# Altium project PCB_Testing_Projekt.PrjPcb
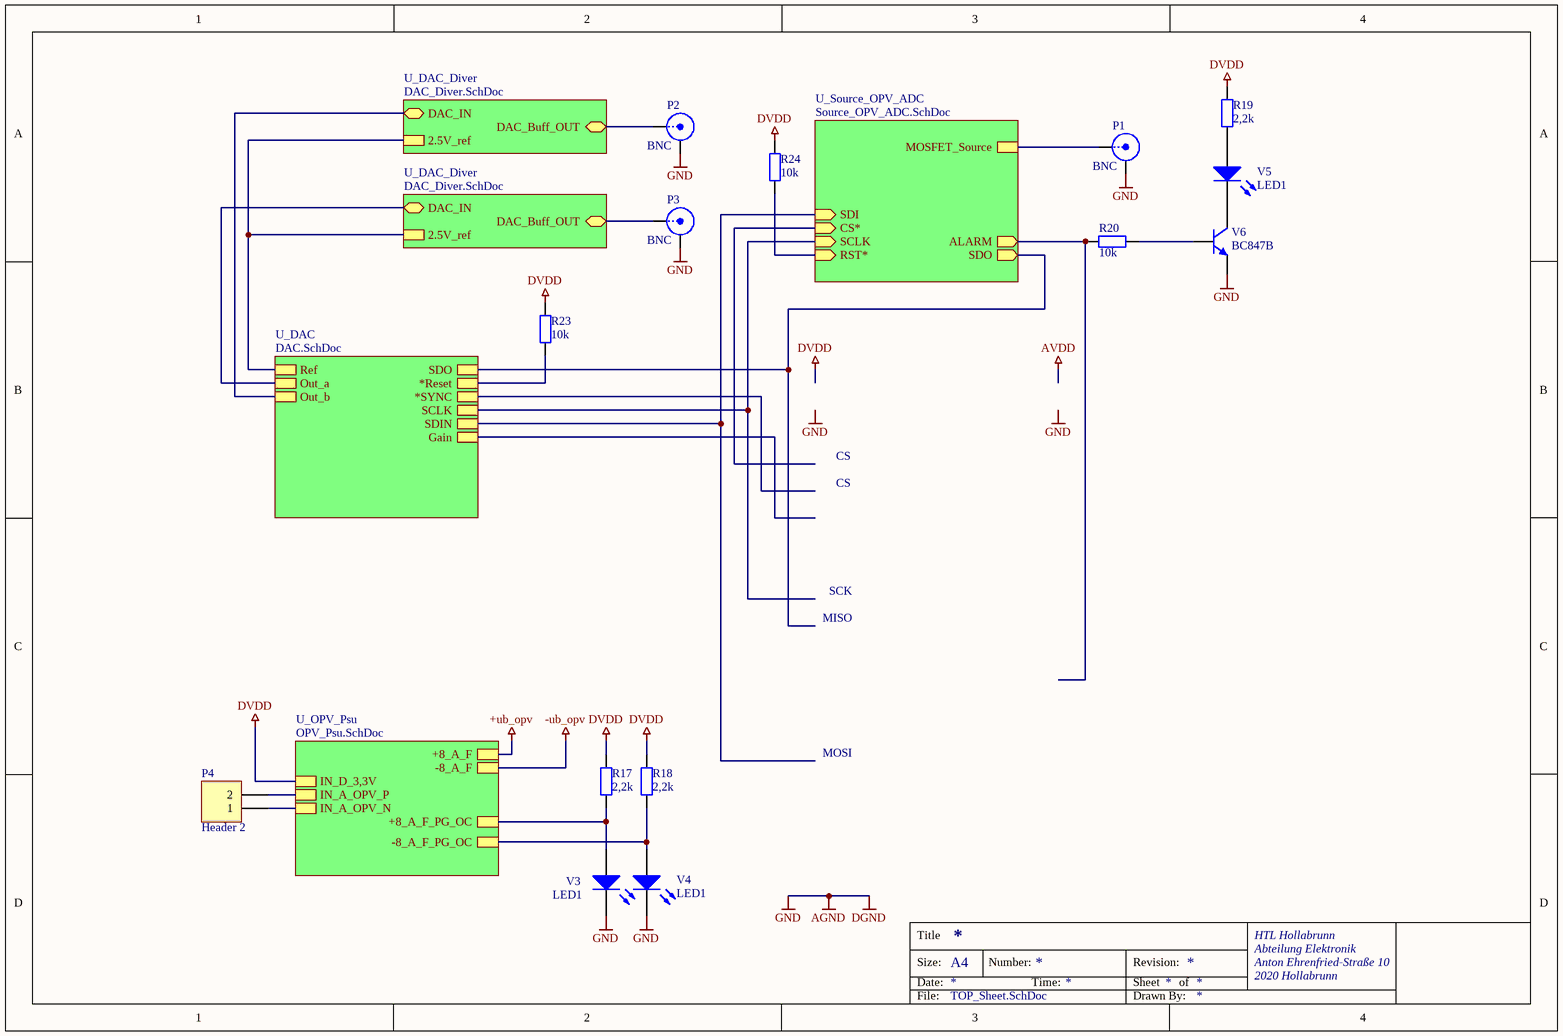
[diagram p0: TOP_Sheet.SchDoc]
5 sheets, 67 parts. Net scope: hierarchical (ports join the sheet entries above them; power ports are global).
Board file: PCB1.PcbDoc
Sheets:
  TOP_Sheet.SchDoc
    U_Source_OPV_ADC = Source_OPV_ADC.SchDoc
    U_OPV_Psu = OPV_Psu.SchDoc
    U_DAC_Diver = DAC_Diver.SchDoc
    U_DAC_Diver = DAC_Diver.SchDoc
    U_DAC = DAC.SchDoc

## Sheet TOP_Sheet.SchDoc
size A4; Organization: HTL Hollabrunn; Address1: Abteilung Elektronik; Address2: Anton Ehrenfried-Straße 10; Address3: 2020 Hollabrunn; SPICEModelCacheBIRIWKQP: <root> / <DocumentId>BIRIWKQP</DocumentId> / <CacheFrame Number="0"> / <Model Name="led1" Kind="MDL"> / <Text>*Typ RED GaAs LED: Vf=1.7V Vr=4V If=40mA trr=3uS / *LED Pinout: 1=A, 2=K / .MODEL LED1 D (IS=93.2P RS=42M N=3.73 BV=4 IBV=10U / + CJO=2.97P VJ=.75 M=.333 TT=4.32U)</Text> / </Model> / <Model Name="qbc847b" Kind="MDL"> / <Text>* / .MODEL QBC847B NPN( / +     IS = 1.822E-14 / +     NF = 0.9932 / +     ISE = 2.894E-16 / +     NE = 1.4 / +     BF = 324.4 / +     IKF = 0.109 / +     VAF = 82 / +     NR = 0.9931 / +     ISC = 9.982E-12 / +     NC = 1.763 / +     BR = 8.29 / +     IKR = 0.09 / +     VAR = 17.9 / +     RB = 10 / +     IRB = 5E-06 / +     RBM = 5 / +     RE = 0.649 / +     RC = 0.7014 / +     XTB = 0 / +     EG = 1.11 / +     XTI = 3 / +     CJE = 1.244E-11 / +     VJE = 0.7579 / +     MJE = 0.3656 / +     TF = 4.908E-10 / +     XTF = 9.51 / +     VTF = 2.927 / +     ITF = 0.3131 / +     PTF = 0 / +     CJC = 3.347E-12 / +     VJC = 0.5463 / +     MJC = 0.391 / +     XCJC = 0.6193 / +     TR = 9E-08 / +     CJS = 0 / +     VJS = 0.75 / +     MJS = 0.333 / +     FC = 0.979)</Text> / </Model> / </CacheFrame> / </root>

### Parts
P1  BNC  [BNC_RA CON]
P2  BNC  [BNC_RA CON]
P3  BNC  [BNC_RA CON]
P4  Header 2  [HDR1X2]
R17  2,2k  [C1206-KUE]
R18  2,2k  [C1206-KUE]
R19  2,2k  [C1206-KUE]
R20  10k  [C1206-KUE]
R23  10k  [C1206-KUE]
R24  10k  [C1206-KUE]
V3  LED1  [LED-1]
V4  LED1  [LED-1]
V5  LED1  [LED-1]
V6  BC847B  [SOT23-KUE]

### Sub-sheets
U_DAC = DAC.SchDoc: Ref, Out_a, Out_b, SDIN, SDO, SCLK, *SYNC, Gain, *Reset
U_DAC_Diver = DAC_Diver.SchDoc: DAC_IN (bidir), DAC_Buff_OUT (bidir), 2.5V_ref
U_DAC_Diver = DAC_Diver.SchDoc: DAC_IN (bidir), DAC_Buff_OUT (bidir), 2.5V_ref
U_OPV_Psu = OPV_Psu.SchDoc: IN_A_OPV_P, +8_A_F, IN_A_OPV_N, IN_D_3,3V, -8_A_F, -8_A_F_PG_OC, +8_A_F_PG_OC
U_Source_OPV_ADC = Source_OPV_ADC.SchDoc: MOSFET_Source, SDI (in), CS* (in), SCLK (in), SDO (out), ALARM (out), RST* (in)

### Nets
AGND: P1.2(Y) P2.2(Y) P3.2(Y) V3.2(K) V4.2(K) V6.2(E)  [also labelled DGND, GND]
DVDD: R17.1 R18.1 R19.1 R23.1 R24.1 ; sheet U_OPV_Psu/IN_D_3,3V  [project net Digital33V]
NetC6_1: P1.1(X) ; sheet U_Source_OPV_ADC/MOSFET_Source
NetC14_2: sheet U_DAC_Diver/2.5V_ref, sheet U_DAC_Diver/2.5V_ref, sheet U_DAC/Ref
NetP2_1: P2.1(X) ; sheet U_DAC_Diver/DAC_Buff_OUT
NetP3_1: P3.1(X) ; sheet U_DAC_Diver/DAC_Buff_OUT
NetP4_1: P4.1 ; sheet U_OPV_Psu/IN_A_OPV_N
NetP4_2: P4.2 ; sheet U_OPV_Psu/IN_A_OPV_P
NetR2_1: R24.2 ; sheet U_Source_OPV_ADC/RST*
NetR7_U_DAC_Diver1_2: sheet U_DAC_Diver/DAC_IN, sheet U_DAC/Out_b
NetR7_U_DAC_Diver2_2: sheet U_DAC_Diver/DAC_IN, sheet U_DAC/Out_a
NetR17_2: R17.2 V3.1(A) ; sheet U_OPV_Psu/+8_A_F_PG_OC
NetR18_2: R18.2 V4.1(A) ; sheet U_OPV_Psu/-8_A_F_PG_OC
NetR19_2: R19.2 V5.1(A)
NetR20_1: R20.1 ; sheet U_Source_OPV_ADC/ALARM
NetR20_2: R20.2 V6.1(B)
NetR23_2: R23.2 ; sheet U_DAC/*Reset
NetU1_10: sheet U_Source_OPV_ADC/SDI, sheet U_DAC/SDIN
NetU1_12: sheet U_Source_OPV_ADC/SCLK, sheet U_DAC/SCLK
NetU1_13: sheet U_Source_OPV_ADC/SDO, sheet U_DAC/SDO
NetV5_2: V5.2(K) V6.3(C)

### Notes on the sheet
- CS
- MISO
- SCK
- MOSI
- Labels drawn without touching a wire or pin: GND

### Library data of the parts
P1-P3 = BNC: BNC Elbow Connector
P4 = Header 2: Header, 2-Pin
R17-R20 R23 R24 = ResistorSMD: Resistor SMD; Manufacturer: AVX; Bezeichnung: SMD Wid. 1/8W 2%
V3-V5 = LED1: Typical RED GaAs LED
V6 = BC847B: NPN General-purpose Transistor SMD; Manufacturer: NXP; Bezeichnung: NPN SMD 45V 0.1A 0.25W

## Sheet Source_OPV_ADC.SchDoc
size A4; Organization: HTL Hollabrunn; Address1: Abteilung Elektronik; Address2: Anton Ehrenfried-Straße 10; Address3: 2020 Hollabrunn; SheetNumber: 1; SheetTotal: 1; SPICEModelCacheDVQSEWCR: <root> / <DocumentId>DVQSEWCR</DocumentId> / <CacheFrame Number="0"> / <Model Name="ua741" Kind="CKT"> / <Text>*==================================================== / *uA741 / *Sngl GenPurpose OpAmp pkg:DIP8 3,2,7,4,6. pkg:CAN8 3,2,7,4,6. / * Connections: / *             Non-Inverting Input / *             ¦ Inverting Input / *             ¦ ¦ Positive Power Supply / *             ¦ ¦ ¦ Negative Power Supply / *             ¦ ¦ ¦ ¦ Output / *             ¦ ¦ ¦ ¦ ¦ / .SUBCKT UA741 1 2 3 4 5 / C1   11 12 4.664E-12 / C2    6  7 20E-12 / DC    5 53 DX / DE   54  5 DX / DLP  90 91 DX / DLN  92 90 DX / DP    4  3 DX / BGND 99  0 V=V(3)*.5 + V(4)*.5 / BB    7 99 I=I(VB)*10.61E6 - I(VC)*10E6 + I(VE)*10E6 + / +              I(VLP)*10E6 - I(VLN)*10E6 / GA    6  0 11 12 137.7E-6 / GCM   0  6 10 99 2.574E-9 / IEE  10  4 DC 10.16E-6 / HLIM 90  0 VLIM 1K / Q1   11  2 13 QX / Q2   12  1 14 QX / R2    6  9 100E3 / RC1   3 11 7.957E3 / RC2   3 12 7.957E3 / RE1  13 10 2.74E3 / RE2  14 10 2.74E3 / REE  10 99 19.69E6 / RO1   8  5 150 / RO2   7 99 150 / RP    3  4 18.11E3 / VB    9  0 DC 0 / VC    3 53 DC 2.6 / VE   54  4 DC 2.6 / VLIM  7  8 DC 0 / VLP  91  0 DC 25 / VLN   0 92 DC 25 / .MODEL DX D(IS=800E-18) / .MODEL QX NPN(IS=800E-18 BF=62.5) / .ENDS UA741</Text> / </Model> / <Model Name="cap" Kind="MDL"> / <Text>*Default semiconductor capacitor / .MODEL CAP C()</Text> / </Model> / </CacheFrame> / </root>
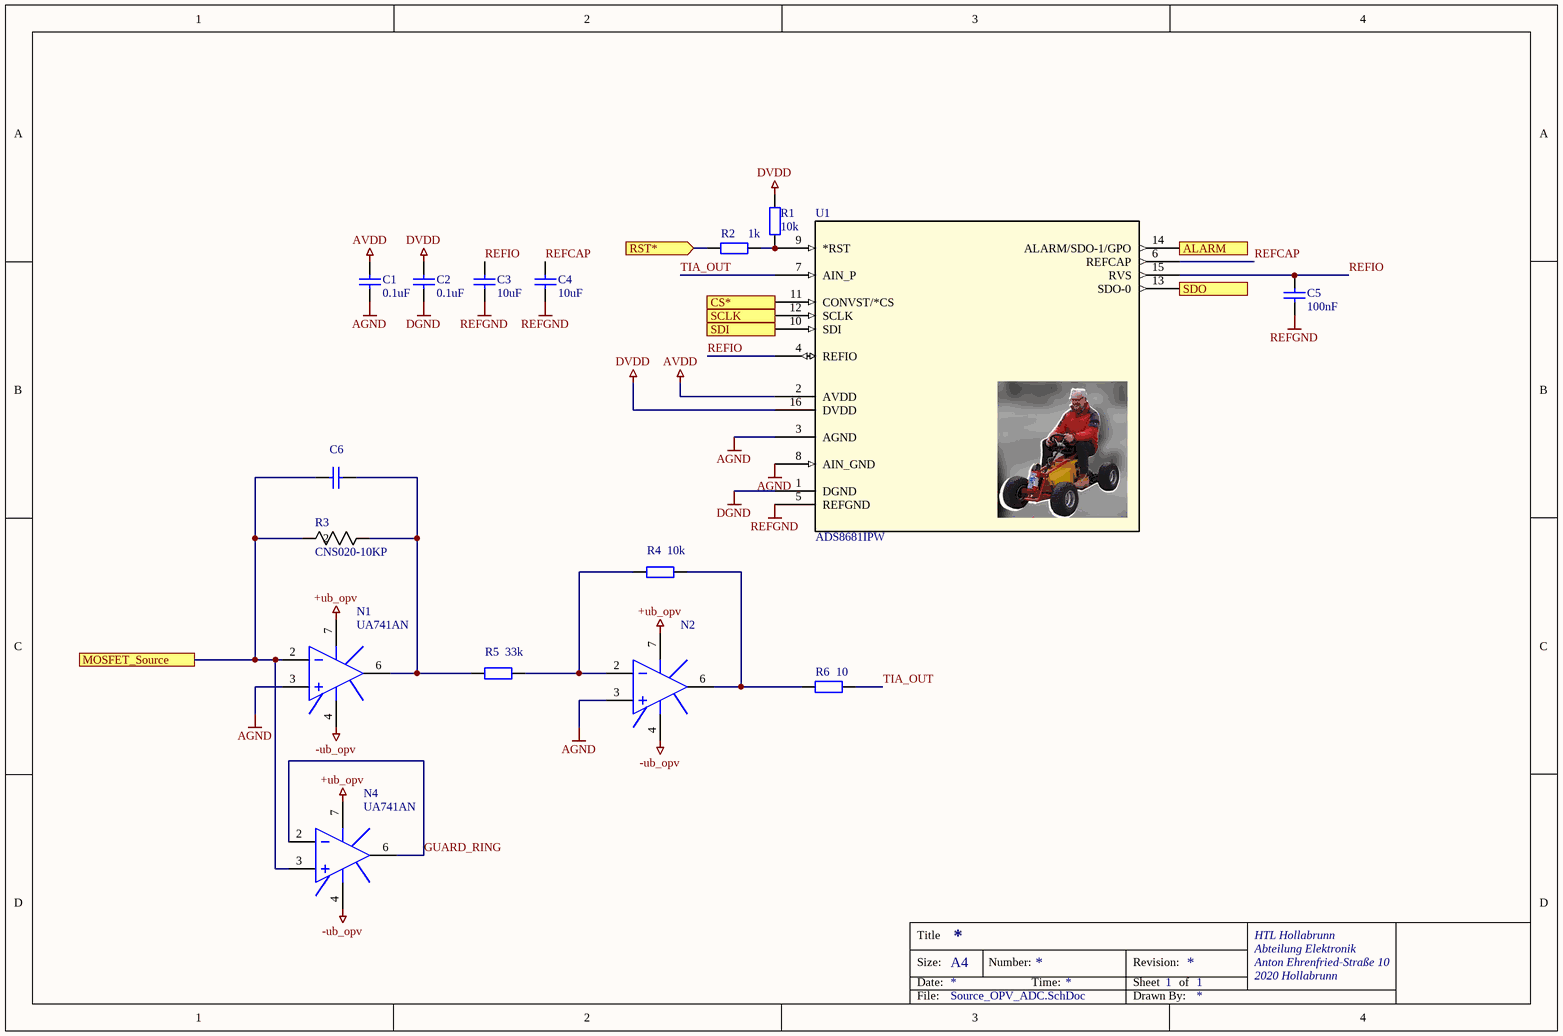
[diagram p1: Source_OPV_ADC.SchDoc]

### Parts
C1  0.1uF  [C1206-KUE]
C2  0.1uF  [C1206-KUE]
C3  10uF  [C1206-KUE]
C4  10uF  [C1206-KUE]
C5  100nF  [C1206-KUE]
C6  100nF  [C1206-KUE]  (value not drawn)
N1  UA741AN  [DIP8]
N2  UA741AN  [DIP8]  (value not drawn)
N4  UA741AN  [DIP8]
R1  10k  [C1206-KUE]
R2  1k  [C1206-KUE]
R3  CNS020-10KP  [RES_CNS020_VIS]
R4  10k  [C1206-KUE]
R5  33k  [C1206-KUE]
R6  10  [C1206-KUE]
U1  ADS8681IPW  [PW16_TEX]

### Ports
ALARM (out), CS* (in), MOSFET_Source, RST* (in), SCLK (in), SDI (in), SDO (out)

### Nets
+ub_opv: N1.7(V+) N2.7(V+) N4.7(V+)  [project net pos_out]
-ub_opv: N1.4(V-) N2.4(V-) N4.4(V-)  [project net neg_out]
AGND: C1.1 C2.1 N1.3(IN+) N2.3(IN+) U1.1(DGND) U1.3(AGND) U1.8(AIN_GND)  [also labelled DGND]
AVDD: C1.2 U1.2(AVDD)
DVDD: C2.2 R1.1 U1.16(DVDD)  [project net Digital33V]
REFGND: C3.1 C4.1 C5.1 U1.5(REFGND)
GUARD_RING: N4.2(IN-) N4.6(OUT)
REFCAP: C4.2 U1.6(REFCAP)
REFIO: C3.2 C5.2 U1.4(REFIO) U1.15(RVS)
TIA_OUT: R6.1 U1.7(AIN_P)
NetC6_1: C6.1 N1.2(IN-) N4.3(IN+) R3.2 ; port MOSFET_Source
NetC6_2: C6.2 N1.6(OUT) R3.1 R5.2
NetN2_2: N2.2(IN-) R4.2 R5.1
NetN2_6: N2.6(OUT) R4.1 R6.2
NetR1_2: R1.2 R2.2 U1.9(*RST)
NetR2_1: R2.1 ; port RST*
NetR20_1: U1.14(ALARM/SDO-1/GPO) ; port ALARM
NetU1_10: U1.10(SDI) ; port SDI
NetU1_11: U1.11(CONVST/*CS) ; port CS*
NetU1_12: U1.12(SCLK) ; port SCLK
NetU1_13: U1.13(SDO-0) ; port SDO

Not connected (* = marked no-connect by the designer): N1 1(OS_NULL) 5(OS_NULL) 8(NC); N2 1(OS_NULL) 5(OS_NULL) 8(NC); N4 1(OS_NULL) 5(OS_NULL) 8(NC)

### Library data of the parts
C1-C6 = Capacitor: Manufacturer: Kemet; Bezeichnung: Kerko +-10% 63V
N1 N2 N4 = UA741AN: General-Purpose Single Operational Amplifier
R1 R2 R4-R6 = ResistorSMD: as R17 on sheet TOP_Sheet
R3 = CNS020-10KP: CNS 020 10K 0,02% e2; Manufacturer_Name: Vishay
U1 = ADS8681IPW: 16-bit, 1MSPS 1-ch SAR ADC with programmable (Â±12V, Â±10V, Â±6V, Â±5V, Â±2.5V) input ranges on 5V supply 16-TSSOP -40 to 125; Manufacturer_Name: Texas Instruments

## Sheet OPV_Psu.SchDoc
size A4; Organization: HTL Hollabrunn; Address1: Abteilung Elektronik; Address2: Anton Ehrenfried-Straße 10; Address3: 2020 Hollabrunn; SPICEModelCacheKALKJBRQ: <root> / <DocumentId>KALKJBRQ</DocumentId> / <CacheFrame Number="0"> / <Model Name="cap" Kind="MDL"> / <Text>*Default semiconductor capacitor / .MODEL CAP C()</Text> / </Model> / <Model Name="qbc847b" Kind="MDL"> / <Text>* / .MODEL QBC847B NPN( / +     IS = 1.822E-14 / +     NF = 0.9932 / +     ISE = 2.894E-16 / +     NE = 1.4 / +     BF = 324.4 / +     IKF = 0.109 / +     VAF = 82 / +     NR = 0.9931 / +     ISC = 9.982E-12 / +     NC = 1.763 / +     BR = 8.29 / +     IKR = 0.09 / +     VAR = 17.9 / +     RB = 10 / +     IRB = 5E-06 / +     RBM = 5 / +     RE = 0.649 / +     RC = 0.7014 / +     XTB = 0 / +     EG = 1.11 / +     XTI = 3 / +     CJE = 1.244E-11 / +     VJE = 0.7579 / +     MJE = 0.3656 / +     TF = 4.908E-10 / +     XTF = 9.51 / +     VTF = 2.927 / +     ITF = 0.3131 / +     PTF = 0 / +     CJC = 3.347E-12 / +     VJC = 0.5463 / +     MJC = 0.391 / +     XCJC = 0.6193 / +     TR = 9E-08 / +     CJS = 0 / +     VJS = 0.75 / +     MJS = 0.333 / +     FC = 0.979)</Text> / </Model> / </CacheFrame> / </root>
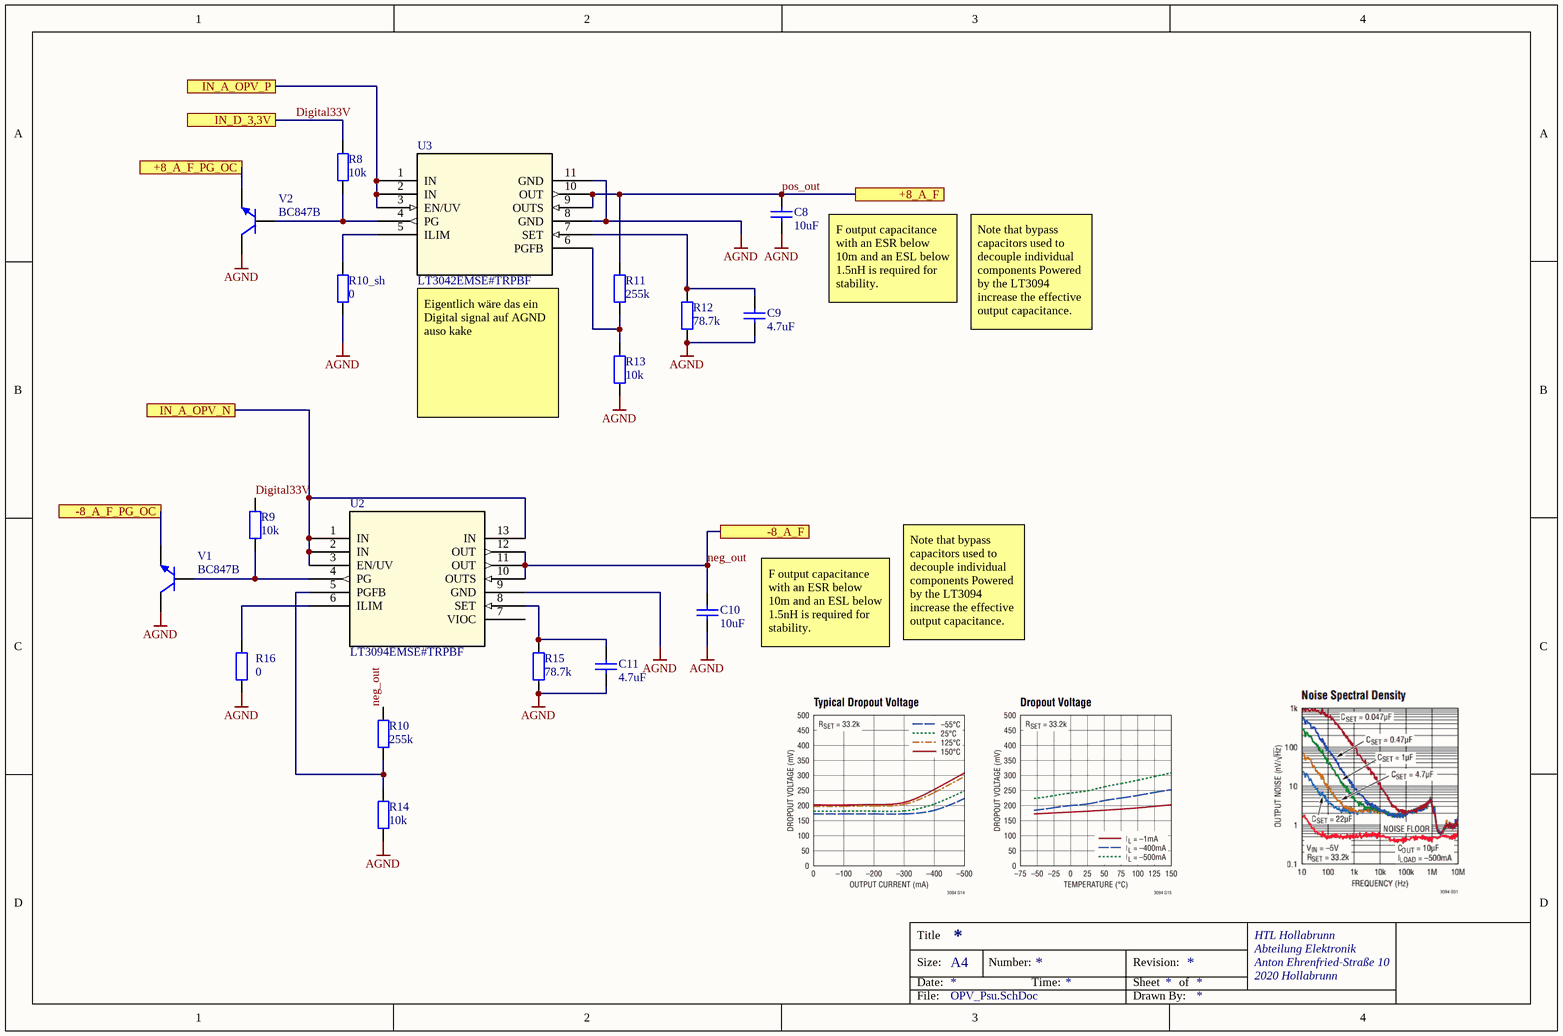
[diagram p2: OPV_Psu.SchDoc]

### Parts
C8  10uF  [C1206-KUE]
C9  4.7uF  [C1206-KUE]
C10  10uF  [C1206-KUE]
C11  4.7uF  [C1206-KUE]
R8  10k  [C1206-KUE]
R9  10k  [C1206-KUE]
R10  255k  [C1206-KUE]
R10_sh  0  [C1206-KUE]
R11  255k  [C1206-KUE]
R12  78.7k  [C1206-KUE]
R13  10k  [C1206-KUE]
R14  10k  [C1206-KUE]
R15  78.7k  [C1206-KUE]
R16  0  [C1206-KUE]
U2  LT3094EMSE#TRPBF  [MSE_05-08-1666_ADI]
U3  LT3042EMSE#TRPBF  [05-08-1664_ADI]
V1  BC847B  [SOT23-KUE]
V2  BC847B  [SOT23-KUE]

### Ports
+8_A_F, +8_A_F_PG_OC, -8_A_F, -8_A_F_PG_OC, IN_A_OPV_N, IN_A_OPV_P, IN_D_3,3V

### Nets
AGND: C8.1 C9.1 C10.1 C11.1 R10_sh.2 R12.2 R13.2 R14.2 R15.2 R16.2 U2.9(GND) U3.8(GND) U3.11(GND) V1.3(C) V2.3(C)
Digital33V: R8.1 R9.1 ; port IN_D_3,3V
neg_out: C10.2 R10.1 U2.10(OUTS) U2.11(OUT) U2.12(OUT) ; port -8_A_F
pos_out: C8.2 R11.1 U3.9(OUTS) U3.10(OUT) ; port +8_A_F
NetC9_2: C9.2 R12.1 U3.7(SET)
NetC11_2: C11.2 R15.1 U2.8(SET)
NetP4_1: U2.1(IN) U2.2(IN) U2.3(EN/UV) U2.13(IN) ; port IN_A_OPV_N
NetP4_2: U3.1(IN) U3.2(IN) U3.3(EN/UV) ; port IN_A_OPV_P
NetR8_2: R8.2 U3.4(PG) V2.1(B)
NetR9_2: R9.2 U2.4(PG) V1.1(B)
NetR10_2: R10.2 R14.1 U2.5(PGFB)
NetR10_sh_1: R10_sh.1 U3.5(ILIM)
NetR11_2: R11.2 R13.1 U3.6(PGFB)
NetR16_1: R16.1 U2.6(ILIM)
NetR17_2: V2.2(E) ; port +8_A_F_PG_OC
NetR18_2: V1.2(E) ; port -8_A_F_PG_OC

Not connected (* = marked no-connect by the designer): U2 7(VIOC)

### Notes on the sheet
- F output capacitance with an ESR below 10m and an ESL below 1.5nH is required for stability.
- Note that bypass capacitors used to decouple individual components Powered by the LT3094 increase the effective output capacitance.
- Eigentlich wäre das ein Digital signal auf AGND auso kake

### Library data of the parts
C8-C11 = Capacitor: as C1 on sheet Source_OPV_ADC
R8-R10 R10_sh R11-R16 = ResistorSMD: as R17 on sheet TOP_Sheet
U2 = LT3094EMSETRPBF: âˆ’20V, 500mA, Ultralow Noise, Ultrahigh PSRR Negative Linear Regulator; Manufacturer_Name: Analog Devices Inc
U3 = LT3042EMSETRPBF: 20V, 200mA, Ultralow Noise, Ultrahigh PSRR RF Linear Regulator; Manufacturer_Name: Analog Devices Inc
V1 V2 = BC847B: as V6 on sheet TOP_Sheet

## Sheet DAC_Diver.SchDoc
size A4; Organization: HTL Hollabrunn; Address1: Abteilung Elektronik; Address2: Anton Ehrenfried-Straße 10; Address3: 2020 Hollabrunn; SPICEModelCacheETVKZAQX: <root> / <DocumentId>ETVKZAQX</DocumentId> / <CacheFrame Number="0"> / <Model Name="cap" Kind="MDL"> / <Text>*Default semiconductor capacitor / .MODEL CAP C()</Text> / </Model> / <Model Name="ua741" Kind="CKT"> / <Text>*==================================================== / *uA741 / *Sngl GenPurpose OpAmp pkg:DIP8 3,2,7,4,6. pkg:CAN8 3,2,7,4,6. / * Connections: / *             Non-Inverting Input / *             ¦ Inverting Input / *             ¦ ¦ Positive Power Supply / *             ¦ ¦ ¦ Negative Power Supply / *             ¦ ¦ ¦ ¦ Output / *             ¦ ¦ ¦ ¦ ¦ / .SUBCKT UA741 1 2 3 4 5 / C1   11 12 4.664E-12 / C2    6  7 20E-12 / DC    5 53 DX / DE   54  5 DX / DLP  90 91 DX / DLN  92 90 DX / DP    4  3 DX / BGND 99  0 V=V(3)*.5 + V(4)*.5 / BB    7 99 I=I(VB)*10.61E6 - I(VC)*10E6 + I(VE)*10E6 + / +              I(VLP)*10E6 - I(VLN)*10E6 / GA    6  0 11 12 137.7E-6 / GCM   0  6 10 99 2.574E-9 / IEE  10  4 DC 10.16E-6 / HLIM 90  0 VLIM 1K / Q1   11  2 13 QX / Q2   12  1 14 QX / R2    6  9 100E3 / RC1   3 11 7.957E3 / RC2   3 12 7.957E3 / RE1  13 10 2.74E3 / RE2  14 10 2.74E3 / REE  10 99 19.69E6 / RO1   8  5 150 / RO2   7 99 150 / RP    3  4 18.11E3 / VB    9  0 DC 0 / VC    3 53 DC 2.6 / VE   54  4 DC 2.6 / VLIM  7  8 DC 0 / VLP  91  0 DC 25 / VLN   0 92 DC 25 / .MODEL DX D(IS=800E-18) / .MODEL QX NPN(IS=800E-18 BF=62.5) / .ENDS UA741</Text> / </Model> / </CacheFrame> / </root>
Used 2 times, as channels U_DAC_Diver, U_DAC_Diver. Parts and nets are listed once, with the designators drawn on the sheet.
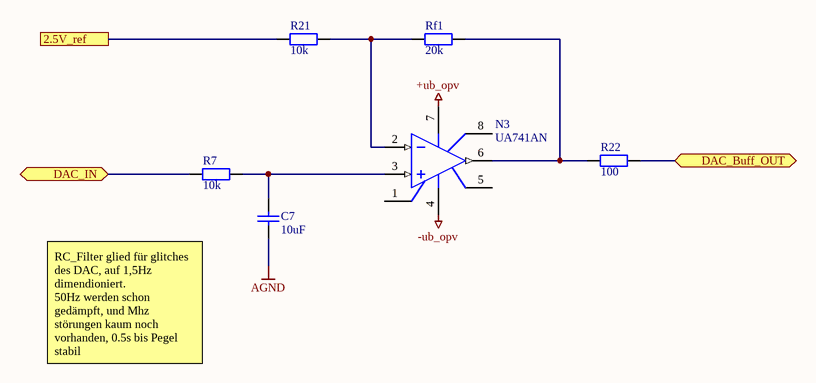
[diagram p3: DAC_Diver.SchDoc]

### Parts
C7  10uF  [C1206-KUE]
N3  UA741AN  [DIP8]
R7  10k  [C1206-KUE]
R21  10k  [C1206-KUE]
R22  100  [C1206-KUE]
Rf1  20k  [C1206-KUE]

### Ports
2.5V_ref, DAC_Buff_OUT (bidir), DAC_IN (bidir)

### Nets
+ub_opv: N3.7(V+)
-ub_opv: N3.4(V-)
AGND: C7.1
2.5V_ref: R21.2 ; port 2.5V_ref
DAC_Buff_OUT: R22.1 ; port DAC_Buff_OUT
DAC_IN: R7.2 ; port DAC_IN
NetC7_2: C7.2 N3.3(IN+) R7.1
NetN3_2: N3.2(IN-) R21.1 Rf1.2
NetN3_6: N3.6(OUT) R22.2 Rf1.1

Not connected (* = marked no-connect by the designer): N3 1(OS_NULL) 5(OS_NULL) 8(NC)

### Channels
U_DAC_Diver: designators end in _U_DAC_Diver2; ports 2.5V_ref=NetC14_2 DAC_Buff_OUT=NetP3_1 DAC_IN=NetR7_U_DAC_Diver2_2
U_DAC_Diver: designators end in _U_DAC_Diver1; ports 2.5V_ref=NetC14_2 DAC_Buff_OUT=NetP2_1 DAC_IN=NetR7_U_DAC_Diver1_2

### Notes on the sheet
- RC_Filter glied für glitches des DAC, auf 1,5Hz dimendioniert.
  50Hz werden schon gedämpft, und Mhz störungen kaum noch vorhanden, 0.5s bis Pegel stabil

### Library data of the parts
C7 = Capacitor: as C1 on sheet Source_OPV_ADC
N3 = UA741AN: as N1 on sheet Source_OPV_ADC
R7 R21 R22 Rf1 = ResistorSMD: as R17 on sheet TOP_Sheet

## Sheet DAC.SchDoc
size A4; Organization: HTL Hollabrunn; Address1: Abteilung Elektronik; Address2: Anton Ehrenfried-Straße 10; Address3: 2020 Hollabrunn; SPICEModelCacheALEDFFPD: <root> / <DocumentId>ALEDFFPD</DocumentId> / <CacheFrame Number="0"> / <Model Name="cap" Kind="MDL"> / <Text>*Default semiconductor capacitor / .MODEL CAP C()</Text> / </Model> / </CacheFrame> / </root>
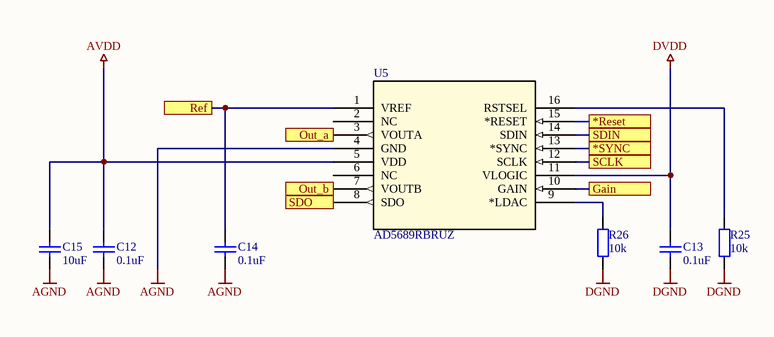
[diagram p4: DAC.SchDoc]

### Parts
C12  0.1uF  [C1206-KUE]
C13  0.1uF  [C1206-KUE]
C14  0.1uF  [C1206-KUE]
C15  10uF  [C1206-KUE]
R25  10k  [C1206-KUE]
R26  10k  [C1206-KUE]
U5  AD5689RBRUZ  [RU_16_ADI]

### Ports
*Reset, *SYNC, Gain, Out_a, Out_b, Ref, SCLK, SDIN, SDO

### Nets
AGND: C12.1 C13.1 C14.1 C15.1 R25.2 R26.2 U5.4(GND)  [also labelled DGND]
AVDD: C12.2 C15.2 U5.5(VDD)
DVDD: C13.2 U5.11(VLOGIC)  [project net Digital33V]
NetC14_2: C14.2 U5.1(VREF) ; port Ref
NetR7_U_DAC_Diver1_2: U5.7(VOUTB) ; port Out_b
NetR7_U_DAC_Diver2_2: U5.3(VOUTA) ; port Out_a
NetR23_2: U5.15(*RESET) ; port *Reset
NetR25_1: R25.1 U5.16(RSTSEL)
NetR26_1: R26.1 U5.9(*LDAC)
NetU1_10: U5.14(SDIN) ; port SDIN
NetU1_12: U5.12(SCLK) ; port SCLK
NetU1_13: U5.8(SDO) ; port SDO
NetU5_10: U5.10(GAIN) ; port Gain
NetU5_13: U5.13(*SYNC) ; port *SYNC

Not connected (* = marked no-connect by the designer): U5 2(NC) 6(NC)

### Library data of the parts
C12-C15 = Capacitor: as C1 on sheet Source_OPV_ADC
R25 R26 = ResistorSMD: as R17 on sheet TOP_Sheet
U5 = AD5689RBRUZ: Dual, 16-Bit nanoDAC+ with 2 ppm/Â°C Reference, SPI Interface; Manufacturer_Name: Analog Devices Inc

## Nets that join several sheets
AGND: TOP_Sheet (6 pins), Source_OPV_ADC (7 pins), OPV_Psu (15 pins), U_DAC_Diver (C7_U_DAC_Diver2.1), U_DAC_Diver (C7_U_DAC_Diver1.1), DAC (7 pins)
AVDD: Source_OPV_ADC (C1.2 U1.2), DAC (C12.2 C15.2 U5.5)
Digital33V: TOP_Sheet (5 pins), Source_OPV_ADC (C2.2 R1.1 U1.16), OPV_Psu (R8.1 R9.1), DAC (C13.2 U5.11)
neg_out: Source_OPV_ADC (N1.4 N2.4 N4.4), OPV_Psu (5 pins), U_DAC_Diver (N3_U_DAC_Diver2.4), U_DAC_Diver (N3_U_DAC_Diver1.4)
pos_out: Source_OPV_ADC (N1.7 N2.7 N4.7), OPV_Psu (C8.2 R11.1 U3.9 U3.10), U_DAC_Diver (N3_U_DAC_Diver2.7), U_DAC_Diver (N3_U_DAC_Diver1.7)
NetC6_1: TOP_Sheet (P1.1), Source_OPV_ADC (C6.1 N1.2 N4.3 R3.2)
NetC14_2: U_DAC_Diver (R21_U_DAC_Diver2.2), U_DAC_Diver (R21_U_DAC_Diver1.2), DAC (C14.2 U5.1)
NetP2_1: TOP_Sheet (P2.1), U_DAC_Diver (R22_U_DAC_Diver1.1)
NetP3_1: TOP_Sheet (P3.1), U_DAC_Diver (R22_U_DAC_Diver2.1)
NetP4_1: TOP_Sheet (P4.1), OPV_Psu (U2.1 U2.2 U2.3 U2.13)
NetP4_2: TOP_Sheet (P4.2), OPV_Psu (U3.1 U3.2 U3.3)
NetR2_1: TOP_Sheet (R24.2), Source_OPV_ADC (R2.1)
NetR7_U_DAC_Diver1_2: U_DAC_Diver (R7_U_DAC_Diver1.2), DAC (U5.7)
NetR7_U_DAC_Diver2_2: U_DAC_Diver (R7_U_DAC_Diver2.2), DAC (U5.3)
NetR17_2: TOP_Sheet (R17.2 V3.1), OPV_Psu (V2.2)
NetR18_2: TOP_Sheet (R18.2 V4.1), OPV_Psu (V1.2)
NetR20_1: TOP_Sheet (R20.1), Source_OPV_ADC (U1.14)
NetR23_2: TOP_Sheet (R23.2), DAC (U5.15)
NetU1_10: Source_OPV_ADC (U1.10), DAC (U5.14)
NetU1_12: Source_OPV_ADC (U1.12), DAC (U5.12)
NetU1_13: Source_OPV_ADC (U1.13), DAC (U5.8)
